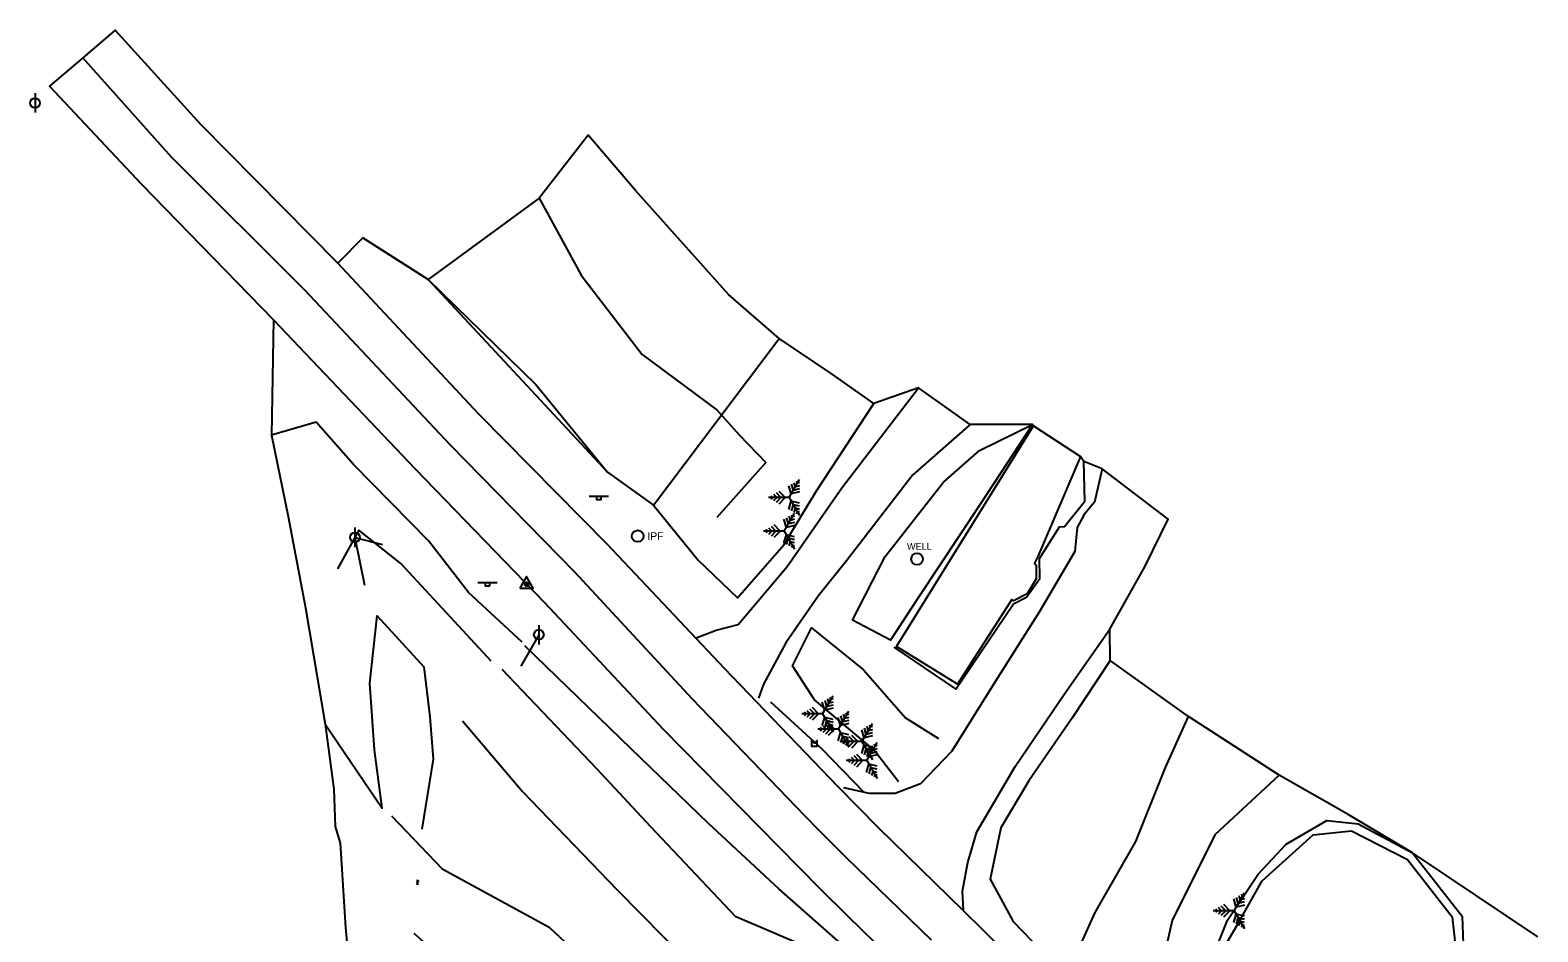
# Model space of a CAD drawing. Extents: x 1158469 to 1165378, y 609843 to 611748.
# Drawn here: x 1158469.5 to 1158857.5, y 611516 to 611748 of the extents above; entities that cross this region are included whole.
import ezdxf

# ---------------------------------------------------------------- set-up
doc = ezdxf.new("R2010")
doc.units = 0
for name, color, linetype in [('Exterior Boundary', 7, 'Continuous'), ('S_Buildings', 7, 'Continuous'), ('S_Control_Temp_Traverse', 7, 'Continuous'), ('S_Drainage_Waterway', 7, 'Continuous'), ('S_Ground_Elevation', 7, 'Continuous'), ('S_Ground_SpotElevation', 7, 'Continuous'), ('S_Property_IronPipeFound', 7, 'Continuous'), ('S_Property_Mailbox', 7, 'Continuous'), ('S_Property_Well_Top', 7, 'Continuous'), ('S_Roadway_Centerline', 7, 'Continuous'), ('S_Roadway_Drive_Gravel', 7, 'Continuous'), ('S_Roadway_Edge_Pavement', 7, 'Continuous'), ('S_Roadway_Edge_Shoulder', 7, 'Continuous'), ('S_Traffic_Sign_SinglePost', 7, 'Continuous'), ('S_Trees_Conifer_Pay', 7, 'Continuous'), ('S_Trees_TreeLine', 7, 'Continuous'), ('S_Utilities_GuyWire3', 7, 'Continuous'), ('S_Utilities_Pole_Power', 7, 'Continuous')]:
    doc.layers.add(name, color=color, linetype=linetype)

msp = doc.modelspace()

# ---------------------------------------------------------------- linework, layer by layer
at = {"layer": 'Exterior Boundary'}
msp.add_lwpolyline([(1158857.5, 611514.75), (1158825.21, 611536.33), (1158808.66, 611546.24), (1158790.91, 611556.33), (1158767.55, 611571.39), (1158747.46, 611585.83), (1158747.32, 611593.91), (1158756.44, 611610.13), (1158762.36, 611622.22), (1158745.34, 611635.17), (1158740.61, 611637), (1158739.82, 611638.31), (1158728.84, 611612.56), (1158727.97, 611610.84), (1158728.38, 611610.33), (1158728.37, 611606.84), (1158726.08, 611602.98), (1158722.57, 611601.17), (1158722.14, 611601.51), (1158708.11, 611579.74), (1158692.39, 611589.47), (1158727.7, 611646.17), (1158727.45, 611646.55), (1158711.43, 611646.54), (1158698.08, 611655.99), (1158686.64, 611651.99), (1158675.84, 611659.53), (1158662.25, 611668.67), (1158649.18, 611679.98), (1158625.22, 611706.72), (1158613.1, 611720.97), (1158600.5, 611704.79), (1158571.92, 611683.83), (1158555.1, 611694.56), (1158548.65, 611688.08), (1158513.41, 611723.76), (1158491.37, 611748.02), (1158482.99, 611740.88), (1158474.44, 611733.57), (1158498.12, 611708.41), (1158532.12, 611673.49), (1158531.61, 611643.8), (1158535.85, 611622.87), (1158540.31, 611599.41), (1158545.37, 611569.43), (1158547.6, 611552.7), (1158547.93, 611543.1), (1158549.23, 611538.85), (1158550.64, 611517.12), (1158552.4, 611497.31)], dxfattribs=at)
at = {"layer": 'S_Buildings'}
msp.add_lwpolyline([(1158739.82, 611638.31), (1158728.84, 611612.56), (1158727.97, 611610.84), (1158728.38, 611610.33), (1158728.37, 611606.84), (1158726.08, 611602.98), (1158722.57, 611601.17), (1158722.14, 611601.51), (1158708.11, 611579.74), (1158692.39, 611589.47), (1158727.7, 611646.17)], close=True, dxfattribs=at)
at = {"layer": 'S_Control_Temp_Traverse'}
for p, q in [((1158597.11, 611605.44), (1158597.36, 611605.44)), ((1158597.23, 611605.57), (1158597.23, 611605.32))]:
    msp.add_line(p, q, dxfattribs=at)
msp.add_lwpolyline([(1158595.5, 611604.44), (1158598.96, 611604.44), (1158597.23, 611607.44)], close=True, dxfattribs=at)
msp.add_circle((1158597.23, 611605.44), 0.5, dxfattribs=at)
at = {"layer": 'S_Drainage_Waterway'}
msp.add_lwpolyline([(1158785.74, 611481.8), (1158777.15, 611489.55), (1158773.6, 611497.1), (1158774.43, 611508), (1158780.14, 611517.71), (1158786.58, 611529.17), (1158799.68, 611540.94), (1158809.55, 611542.02), (1158823.95, 611534.62), (1158835.49, 611519.84), (1158836.62, 611508.98), (1158834.58, 611499.17), (1158830.73, 611491.78), (1158824.45, 611483.92), (1158813.6, 611474.99), (1158803.06, 611473.68)], close=True, dxfattribs=at)
at = {"layer": 'S_Ground_Elevation'}
for points in [[(1158555.1, 611694.56), (1158571.92, 611683.83), (1158599.6, 611656.8), (1158618.07, 611634.31), (1158629.91, 611625.78), (1158641.36, 611611.66), (1158651.53, 611601.98), (1158663.4, 611615.61), (1158671.81, 611629.5), (1158686.64, 611651.99), (1158675.84, 611659.53), (1158662.25, 611668.67), (1158649.18, 611679.98), (1158625.22, 611706.72), (1158613.1, 611720.97), (1158600.5, 611704.79), (1158611.25, 611684.95), (1158626.99, 611664.6), (1158646.26, 611650.21), (1158651.92, 611643.86), (1158658.81, 611636.73), (1158646.21, 611622.59)], [(1158596.09, 611590.55), (1158582.31, 611603.32), (1158572.02, 611616.64), (1158552.71, 611636.27), (1158543.07, 611647.12), (1158531.61, 611643.8), (1158535.85, 611622.87), (1158540.31, 611599.41), (1158545.37, 611569.43), (1158560.06, 611547.81), (1158558.05, 611562.82), (1158556.9, 611579.95), (1158558.76, 611597.28), (1158570.78, 611584.18), (1158572.35, 611571.31), (1158573.14, 611560.48), (1158570.25, 611542.42)], [(1158691.78, 611589.23), (1158707.73, 611578.47), (1158722.56, 611600.43), (1158725.9, 611602.13), (1158729.32, 611606.9), (1158729.21, 611612.08), (1158734.42, 611620.24), (1158735.65, 611620.32), (1158740.92, 611626.83), (1158740.61, 611637)], [(1158588.11, 611585.67), (1158577.6, 611596.95), (1158564.86, 611610.77), (1158554.09, 611619.4), (1158548.56, 611609.38)], [(1158692.94, 611554.57), (1158686.64, 611562.86), (1158671.35, 611575.74), (1158665.7, 611584.49), (1158670.52, 611594.21), (1158683.95, 611583.43), (1158694.78, 611571.08), (1158703.26, 611565.77)], [(1158740.09, 611448.28), (1158722.35, 611464.08), (1158707.31, 611475.97), (1158698.09, 611489.64), (1158689.14, 611501.5), (1158678.07, 611512.98), (1158662.14, 611527.03), (1158643.93, 611543.97), (1158624.15, 611563.13), (1158596.77, 611589.62)], [(1158808.66, 611546.24), (1158790.91, 611556.33), (1158774.35, 611541), (1158763.38, 611518.91), (1158758.8, 611498.89), (1158763.92, 611486.74), (1158760.8, 611483.29), (1158748.32, 611494.91), (1158736.46, 611505.19), (1158743.56, 611521.02), (1158754.04, 611539.22), (1158761.64, 611558.27), (1158767.55, 611571.39), (1158747.46, 611585.83), (1158737.58, 611570.89), (1158726.51, 611554.87), (1158719.26, 611542.74), (1158716.56, 611529.56), (1158722.45, 611518.66), (1158729.61, 611511.28)], [(1158590.85, 611583.59), (1158615.18, 611558.04), (1158629.09, 611543.1), (1158650.93, 611520), (1158669.17, 611512.21), (1158688.09, 611487.97), (1158694.7, 611477.56), (1158707.55, 611459.8), (1158720.85, 611445.22), (1158707.76, 611420.56), (1158699.39, 611413.61), (1158682.9, 611426.67), (1158670.67, 611439.15), (1158654.72, 611451.38), (1158635.01, 611471.5), (1158613.25, 611484.43), (1158585.12, 611500.58), (1158568.33, 611515.58)], [(1158580.71, 611570.3), (1158596.17, 611552.09), (1158620.52, 611526.83), (1158638.48, 611508.6), (1158660.2, 611498.31), (1158675.5, 611480.75), (1158687.22, 611466.53), (1158694.73, 611452.55), (1158709.71, 611440.16), (1158700.35, 611433.55), (1158684.85, 611447.82), (1158665.43, 611464.41), (1158653.02, 611480.25), (1158622.81, 611498.8), (1158603.19, 611517), (1158575.66, 611532.02), (1158562.58, 611545.77)], [(1158774.24, 611487.44), (1158773.21, 611508.05), (1158777.62, 611519.03), (1158785.53, 611530.88), (1158792.69, 611538.6), (1158803.21, 611544.63), (1158811.27, 611543.77), (1158825.21, 611536.33), (1158838.01, 611520.07), (1158838.43, 611508.04), (1158836.52, 611498.69), (1158831.59, 611491.44), (1158826.6, 611482.59)]]:
    msp.add_lwpolyline(points, dxfattribs=at)
msp.add_lwpolyline([(1158727.45, 611646.55), (1158714.04, 611626.16), (1158698.05, 611601.93), (1158690.9, 611591.04), (1158681.09, 611596.17), (1158689.54, 611612.58), (1158704.46, 611631.61), (1158713.82, 611639.88)], close=True, dxfattribs=at)
at = {"layer": 'S_Ground_SpotElevation'}
for p, q in [((1158569.38, 611529.19), (1158568.85, 611528.4)), ((1158568.85, 611528.4), (1158569.38, 611528.4)), ((1158568.86, 611529.19), (1158569.38, 611529.19)), ((1158568.96, 611528.8), (1158569.27, 611528.8))]:
    msp.add_line(p, q, dxfattribs=at)
at = {"layer": 'S_Property_IronPipeFound'}
msp.add_circle((1158625.82, 611617.84), 1.5, dxfattribs=at)
at = {"layer": 'S_Property_Mailbox'}
msp.add_lwpolyline([(1158670.52, 611565.27), (1158670.52, 611563.77), (1158672.02, 611563.77), (1158672.02, 611565.27), (1158671.27, 611564.52)], close=True, dxfattribs=at)
at = {"layer": 'S_Property_Well_Top'}
msp.add_circle((1158697.72, 611611.94), 1.5, dxfattribs=at)
at = {"layer": 'S_Roadway_Centerline'}
msp.add_lwpolyline([(1158701.46, 611513.88), (1158679.55, 611535.06), (1158672.37, 611542.24), (1158668.82, 611545.88), (1158639.86, 611575.92), (1158609.64, 611608.52), (1158577.53, 611641.32), (1158540.19, 611681.12), (1158505.84, 611715.38), (1158482.99, 611740.88)], dxfattribs=at)
at = {"layer": 'S_Roadway_Drive_Gravel'}
for points in [[(1158640.85, 611591.65), (1158646, 611593.62), (1158651.68, 611595.08), (1158664.3, 611610.05), (1158678.39, 611630.29), (1158698.08, 611655.99)], [(1158711.43, 611646.54), (1158696.62, 611633.61), (1158679.58, 611611.47), (1158672.25, 611602.42), (1158663.92, 611590.39), (1158658.17, 611579.7), (1158656.93, 611576.17)], [(1158745.34, 611635.17), (1158743.39, 611626.57), (1158740.76, 611623.37), (1158738.95, 611620.08), (1158738.34, 611613.83), (1158729.15, 611598.24), (1158717.45, 611579.79), (1158706.69, 611562.48), (1158698.63, 611554.11), (1158692.06, 611551.64), (1158685.48, 611551.6), (1158678.84, 611553.08)], [(1158709.69, 611521.6), (1158709.44, 611526.47), (1158710.79, 611533.84), (1158713.15, 611541.71), (1158722.97, 611558.55), (1158735.66, 611577.27), (1158747.32, 611593.91), (1158756.44, 611610.13), (1158762.36, 611622.22)]]:
    msp.add_lwpolyline(points, dxfattribs=at)
at = {"layer": 'S_Roadway_Edge_Pavement'}
for points in [[(1158725.73, 611505.63), (1158709.47, 611521.56), (1158687.92, 611542.65), (1158677.34, 611553.39), (1158648.14, 611583.75), (1158618.03, 611615.7), (1158584.92, 611649.25), (1158548.65, 611688.08), (1158513.41, 611723.76), (1158491.37, 611748.02)], [(1158694.13, 611506.17), (1158679.83, 611520.15), (1158672.73, 611527.19), (1158662.16, 611537.84), (1158632.48, 611568.11), (1158601.94, 611600.69), (1158568.63, 611635.08), (1158532.12, 611673.49), (1158498.12, 611708.41), (1158474.44, 611733.57)]]:
    msp.add_lwpolyline(points, dxfattribs=at)
at = {"layer": 'S_Roadway_Edge_Shoulder'}
msp.add_lwpolyline([(1158684.1, 611551.89), (1158673.32, 611562.98), (1158660.09, 611575.13)], dxfattribs=at)
at = {"layer": 'S_Traffic_Sign_SinglePost'}
for p, q in [((1158613.3, 611628.15), (1158618.3, 611628.15)), ((1158584.69, 611605.92), (1158589.69, 611605.92))]:
    msp.add_line(p, q, dxfattribs=at)
for points in [[(1158615.3, 611628.15), (1158616.3, 611628.15), (1158616.3, 611627.15), (1158615.3, 611627.15)], [(1158586.69, 611605.92), (1158587.69, 611605.92), (1158587.69, 611604.92), (1158586.69, 611604.92)]]:
    msp.add_lwpolyline(points, close=True, dxfattribs=at)
at = {"layer": 'S_Trees_Conifer_Pay'}
for p, q in [((1158664.83, 611627.75), (1158667.5, 611632.37)), ((1158666.43, 611630.52), (1158666.13, 611631.58)), ((1158666.96, 611631.45), (1158666.81, 611631.98)), ((1158667.5, 611631.58), (1158666.96, 611631.45)), ((1158664.83, 611627.75), (1158659.49, 611627.75)), ((1158660.56, 611627.75), (1158660.18, 611628.15)), ((1158660.18, 611627.36), (1158660.56, 611627.75)), ((1158661.63, 611627.75), (1158660.87, 611628.54)), ((1158660.87, 611626.96), (1158661.63, 611627.75)), ((1158662.7, 611627.75), (1158661.55, 611628.94)), ((1158661.55, 611626.56), (1158662.7, 611627.75)), ((1158663.76, 611627.75), (1158662.24, 611629.34)), ((1158662.24, 611626.17), (1158663.76, 611627.75)), ((1158665.36, 611628.68), (1158664.75, 611630.79)), ((1158664.83, 611627.75), (1158667.5, 611623.13)), ((1158667.5, 611629.2), (1158665.36, 611628.68)), ((1158665.9, 611629.6), (1158665.44, 611631.18)), ((1158667.5, 611630), (1158665.9, 611629.6)), ((1158667.5, 611630.79), (1158666.43, 611630.52)), ((1158663.55, 611619.12), (1158666.22, 611623.74)), ((1158664.75, 611624.72), (1158665.36, 611626.83)), ((1158667.5, 611626.3), (1158665.36, 611626.83)), ((1158665.44, 611624.32), (1158665.9, 611625.9)), ((1158667.5, 611625.51), (1158665.9, 611625.9)), ((1158666.13, 611623.92), (1158666.43, 611624.98)), ((1158667.5, 611624.72), (1158666.43, 611624.98)), ((1158666.81, 611623.53), (1158666.96, 611624.06)), ((1158667.5, 611623.92), (1158666.96, 611624.06)), ((1158660.35, 611619.12), (1158659.58, 611619.91)), ((1158661.41, 611619.12), (1158660.27, 611620.3)), ((1158662.48, 611619.12), (1158660.96, 611620.7)), ((1158664.08, 611620.04), (1158663.47, 611622.15)), ((1158666.22, 611620.57), (1158664.08, 611620.04)), ((1158664.61, 611620.96), (1158664.16, 611622.55)), ((1158666.22, 611621.36), (1158664.61, 611620.96)), ((1158665.14, 611621.89), (1158664.84, 611622.94)), ((1158666.22, 611622.15), (1158665.14, 611621.89)), ((1158665.68, 611622.81), (1158665.53, 611623.34)), ((1158666.22, 611622.94), (1158665.68, 611622.81)), ((1158663.55, 611619.12), (1158658.21, 611619.12)), ((1158659.28, 611619.12), (1158658.9, 611619.51)), ((1158658.9, 611618.72), (1158659.28, 611619.12)), ((1158659.58, 611618.32), (1158660.35, 611619.12)), ((1158660.27, 611617.93), (1158661.41, 611619.12)), ((1158660.96, 611617.53), (1158662.48, 611619.12)), ((1158663.47, 611616.08), (1158664.08, 611618.19)), ((1158663.55, 611619.12), (1158666.22, 611614.5)), ((1158666.22, 611617.66), (1158664.08, 611618.19)), ((1158664.16, 611615.68), (1158664.61, 611617.27)), ((1158666.22, 611616.87), (1158664.61, 611617.27)), ((1158664.84, 611615.29), (1158665.14, 611616.34)), ((1158666.22, 611616.08), (1158665.14, 611616.34)), ((1158665.53, 611614.89), (1158665.68, 611615.42)), ((1158666.22, 611615.29), (1158665.68, 611615.42)), ((1158671.29, 611572.11), (1158670.14, 611573.29)), ((1158672.35, 611572.11), (1158670.83, 611573.69)), ((1158673.95, 611573.03), (1158673.34, 611575.14)), ((1158673.42, 611572.11), (1158676.09, 611576.73)), ((1158676.09, 611573.56), (1158673.95, 611573.03)), ((1158674.49, 611573.95), (1158674.03, 611575.54)), ((1158676.09, 611574.35), (1158674.49, 611573.95)), ((1158675.02, 611574.88), (1158674.72, 611575.93)), ((1158676.09, 611575.14), (1158675.02, 611574.88)), ((1158675.55, 611575.8), (1158675.4, 611576.33)), ((1158676.09, 611575.93), (1158675.55, 611575.8)), ((1158673.42, 611572.11), (1158668.08, 611572.11)), ((1158669.15, 611572.11), (1158668.77, 611572.5)), ((1158668.77, 611571.71), (1158669.15, 611572.11)), ((1158670.22, 611572.11), (1158669.46, 611572.9)), ((1158669.46, 611571.31), (1158670.22, 611572.11)), ((1158670.14, 611570.92), (1158671.29, 611572.11)), ((1158670.83, 611570.52), (1158672.35, 611572.11)), ((1158673.34, 611569.07), (1158673.95, 611571.18)), ((1158673.42, 611572.11), (1158676.09, 611567.49)), ((1158676.09, 611570.65), (1158673.95, 611571.18)), ((1158674.03, 611568.67), (1158674.49, 611570.26)), ((1158675.39, 611568.16), (1158674.25, 611569.35)), ((1158676.09, 611569.86), (1158674.49, 611570.26)), ((1158674.72, 611568.28), (1158675.02, 611569.33)), ((1158676.46, 611568.16), (1158674.94, 611569.75)), ((1158676.09, 611569.07), (1158675.02, 611569.33)), ((1158678.06, 611569.09), (1158677.45, 611571.2)), ((1158677.53, 611568.16), (1158680.2, 611572.78)), ((1158680.2, 611569.61), (1158678.06, 611569.09)), ((1158678.6, 611570.01), (1158678.14, 611571.59)), ((1158680.2, 611570.41), (1158678.6, 611570.01)), ((1158679.13, 611570.93), (1158678.82, 611571.99)), ((1158680.2, 611571.2), (1158679.13, 611570.93)), ((1158679.66, 611571.86), (1158679.51, 611572.39)), ((1158680.2, 611571.99), (1158679.66, 611571.86)), ((1158683.55, 611564.97), (1158686.22, 611569.59)), ((1158677.53, 611568.16), (1158672.19, 611568.16)), ((1158673.26, 611568.16), (1158672.88, 611568.56)), ((1158672.88, 611567.77), (1158673.26, 611568.16)), ((1158674.33, 611568.16), (1158673.57, 611568.95)), ((1158673.57, 611567.37), (1158674.33, 611568.16)), ((1158674.25, 611566.97), (1158675.39, 611568.16)), ((1158674.94, 611566.58), (1158676.46, 611568.16)), ((1158675.4, 611567.88), (1158675.55, 611568.41)), ((1158676.09, 611568.28), (1158675.55, 611568.41)), ((1158677.45, 611565.13), (1158678.06, 611567.24)), ((1158677.53, 611568.16), (1158680.2, 611563.54)), ((1158680.2, 611566.71), (1158678.06, 611567.24)), ((1158678.14, 611564.73), (1158678.6, 611566.31)), ((1158680.2, 611565.92), (1158678.6, 611566.31)), ((1158680.35, 611564.97), (1158679.58, 611565.76)), ((1158681.41, 611564.97), (1158680.27, 611566.16)), ((1158682.48, 611564.97), (1158680.96, 611566.55)), ((1158684.08, 611565.89), (1158683.47, 611568)), ((1158686.22, 611566.42), (1158684.08, 611565.89)), ((1158684.61, 611566.82), (1158684.16, 611568.4)), ((1158686.22, 611567.21), (1158684.61, 611566.82)), ((1158685.14, 611567.74), (1158684.84, 611568.8)), ((1158686.22, 611568), (1158685.14, 611567.74)), ((1158685.68, 611568.66), (1158685.53, 611569.19)), ((1158686.22, 611568.8), (1158685.68, 611568.66)), ((1158683.55, 611564.97), (1158678.21, 611564.97)), ((1158678.82, 611564.33), (1158679.13, 611565.39)), ((1158679.28, 611564.97), (1158678.9, 611565.36)), ((1158678.9, 611564.57), (1158679.28, 611564.97)), ((1158680.2, 611565.13), (1158679.13, 611565.39)), ((1158679.51, 611563.94), (1158679.66, 611564.47)), ((1158679.58, 611564.18), (1158680.35, 611564.97)), ((1158680.2, 611564.33), (1158679.66, 611564.47)), ((1158680.27, 611563.78), (1158681.41, 611564.97)), ((1158680.96, 611563.38), (1158682.48, 611564.97)), ((1158683.72, 611560.07), (1158682.2, 611561.66)), ((1158683.47, 611561.93), (1158684.08, 611564.04)), ((1158683.55, 611564.97), (1158686.22, 611560.35)), ((1158686.22, 611563.52), (1158684.08, 611564.04)), ((1158684.16, 611561.54), (1158684.61, 611563.12)), ((1158686.22, 611562.72), (1158684.61, 611563.12)), ((1158685.32, 611561), (1158684.72, 611563.11)), ((1158684.79, 611560.07), (1158687.46, 611564.69)), ((1158684.84, 611561.14), (1158685.14, 611562.2)), ((1158686.22, 611561.93), (1158685.14, 611562.2)), ((1158685.86, 611561.92), (1158685.4, 611563.5)), ((1158687.46, 611562.32), (1158685.86, 611561.92)), ((1158686.39, 611562.84), (1158686.09, 611563.9)), ((1158687.46, 611563.11), (1158686.39, 611562.84)), ((1158686.92, 611563.77), (1158686.77, 611564.3)), ((1158687.46, 611563.9), (1158686.92, 611563.77)), ((1158684.79, 611560.07), (1158679.46, 611560.07)), ((1158680.52, 611560.07), (1158680.14, 611560.47)), ((1158680.14, 611559.68), (1158680.52, 611560.07)), ((1158681.59, 611560.07), (1158680.83, 611560.86)), ((1158680.83, 611559.28), (1158681.59, 611560.07)), ((1158682.66, 611560.07), (1158681.51, 611561.26)), ((1158681.51, 611558.88), (1158682.66, 611560.07)), ((1158682.2, 611558.49), (1158683.72, 611560.07)), ((1158684.72, 611557.04), (1158685.32, 611559.15)), ((1158684.79, 611560.07), (1158687.46, 611555.45)), ((1158687.46, 611561.52), (1158685.32, 611561)), ((1158687.46, 611558.62), (1158685.32, 611559.15)), ((1158685.4, 611556.64), (1158685.86, 611558.22)), ((1158685.53, 611560.74), (1158685.68, 611561.27)), ((1158686.22, 611561.14), (1158685.68, 611561.27)), ((1158687.46, 611557.83), (1158685.86, 611558.22)), ((1158686.09, 611556.24), (1158686.39, 611557.3)), ((1158687.46, 611557.04), (1158686.39, 611557.3)), ((1158686.77, 611555.85), (1158686.92, 611556.38)), ((1158687.46, 611556.24), (1158686.92, 611556.38)), ((1158778.23, 611521.45), (1158776.71, 611523.03)), ((1158779.83, 611522.37), (1158779.23, 611524.48)), ((1158779.3, 611521.45), (1158781.97, 611526.07)), ((1158781.97, 611522.9), (1158779.83, 611522.37)), ((1158780.37, 611523.3), (1158779.91, 611524.88)), ((1158781.97, 611523.69), (1158780.37, 611523.3)), ((1158780.9, 611524.22), (1158780.6, 611525.28)), ((1158781.97, 611524.48), (1158780.9, 611524.22)), ((1158781.43, 611525.14), (1158781.28, 611525.67)), ((1158781.97, 611525.28), (1158781.43, 611525.14)), ((1158779.3, 611521.45), (1158773.97, 611521.45)), ((1158775.03, 611521.45), (1158774.65, 611521.84)), ((1158774.65, 611521.05), (1158775.03, 611521.45)), ((1158776.1, 611521.45), (1158775.34, 611522.24)), ((1158775.34, 611520.66), (1158776.1, 611521.45)), ((1158777.17, 611521.45), (1158776.02, 611522.64)), ((1158776.02, 611520.26), (1158777.17, 611521.45)), ((1158776.71, 611519.86), (1158778.23, 611521.45)), ((1158779.23, 611518.41), (1158779.83, 611520.52)), ((1158779.3, 611521.45), (1158781.97, 611516.83)), ((1158781.97, 611520), (1158779.83, 611520.52)), ((1158779.91, 611518.02), (1158780.37, 611519.6)), ((1158781.97, 611519.2), (1158780.37, 611519.6)), ((1158780.6, 611517.62), (1158780.9, 611518.68)), ((1158781.97, 611518.41), (1158780.9, 611518.68)), ((1158781.28, 611517.22), (1158781.43, 611517.75)), ((1158781.97, 611517.62), (1158781.43, 611517.75))]:
    msp.add_line(p, q, dxfattribs=at)
at = {"layer": 'S_Trees_TreeLine'}
msp.add_lwpolyline([(1158555.1, 611694.56), (1158571.92, 611683.83), (1158618.07, 611634.31), (1158629.91, 611625.78), (1158662.25, 611668.67)], dxfattribs=at)
at = {"layer": 'S_Utilities_GuyWire3'}
for points in [[(1158553.05, 611617.51), (1158560.18, 611615.66)], [(1158553.05, 611617.51), (1158555.52, 611605.2)], [(1158600.37, 611592.45), (1158595.72, 611584.35)]]:
    msp.add_lwpolyline(points, dxfattribs=at)
at = {"layer": 'S_Utilities_Pole_Power'}
for p, q in [((1158470.7, 611731.8), (1158470.7, 611726.8)), ((1158553.05, 611620.01), (1158553.05, 611615.01)), ((1158600.37, 611594.95), (1158600.37, 611589.95))]:
    msp.add_line(p, q, dxfattribs=at)
for centre in [(1158470.7, 611729.3), (1158553.05, 611617.51), (1158600.37, 611592.45)]:
    msp.add_circle(centre, 1.25, dxfattribs=at)

# ---------------------------------------------------------------- texts
at = {"layer": 'S_Property_IronPipeFound'}
msp.add_text('IPF', height=2, dxfattribs=at).set_placement((1158628.32, 611616.84))
at = {"layer": 'S_Property_Well_Top'}
msp.add_text('WELL', height=1.75, rotation=360, dxfattribs=at).set_placement((1158695.14, 611614.31))

doc.saveas('drawing.dxf')
